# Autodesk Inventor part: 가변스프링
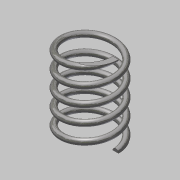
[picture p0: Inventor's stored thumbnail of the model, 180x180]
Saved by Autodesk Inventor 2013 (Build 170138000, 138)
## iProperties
Created: 2017-12
Part Number: 가변스프링
Material: 스테인리스강
Document SubType Name: Modeling
Designer: Administrator
Mass: 7.07442 g
Surface Area: 17.742 cm^2
Volume: 0.875547 cm^3
Density: 8.08 g/cm^3
Author: Administrator
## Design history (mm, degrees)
sketch "스케치1"
  geometry: L1 (0, 0)-(9, 0); L2 (9, 0)-(9, 28.5); L3 (9, 28.5)-(0, 28.5); L4 (0, 28.5)-(0, 0); C1 r 1 at (9, 0)
  constraints: 8 end point, 2 parallel, 1 centre point, 1 coincident, 1 horizontal, 1 perpendicular
  dimensions: "d0" = 18 diameter of L2 L4; "d2" = 28.5 distance of L1.end L2.end (derived); "d3" = 2 diameter of C1
feature "코일1" sketch "스케치1" pitch "d4" = 10; turns "d6" = 5; dims "d5" = 28.5 (= d2), "d7" = 0, angle "d8" = 90 deg, angle "d9" = 90 deg, "d10" = 0, "d11" = 0
node "작업 평면1"
sketch "스케치2"
  geometry: L1 (1, 0)-(-1, 0) reference; 1 further point
  constraints: 1 horizontal alignment
extrude "돌출1" cut sketch "스케치2" distance "d12" = 10; taper "d13" = 0 deg
node "작업 평면2"
sketch "스케치3"
  geometry: L1 (-1, 0)-(1, 0) reference; 1 further point
  constraints: 1 horizontal alignment
extrude "돌출2" cut sketch "스케치3" distance "d14" = 10; taper "d15" = 0 deg
node "솔리드1"
node "절단 모서리 투영1"
node "절단 모서리 투영2"
